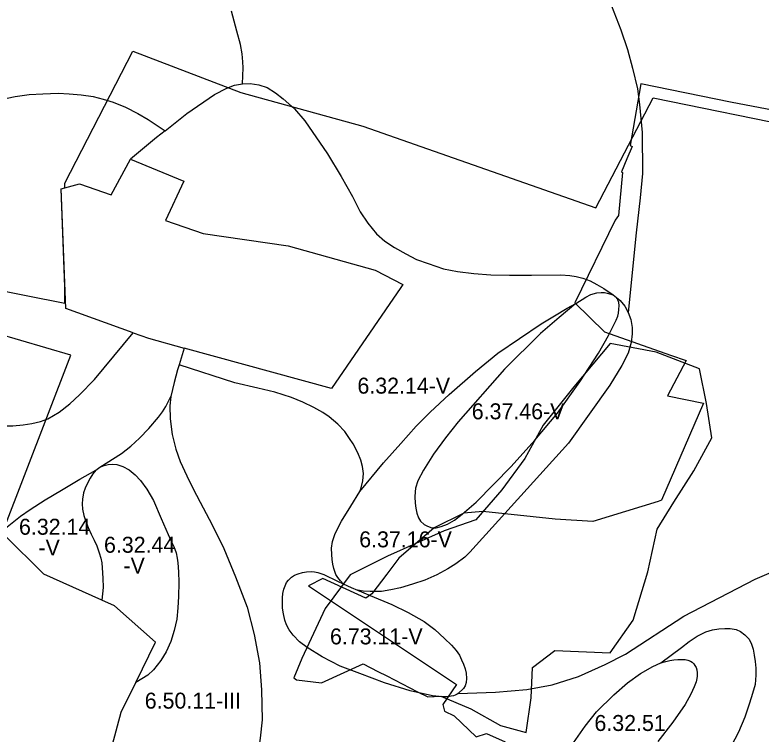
# Model space of a CAD drawing. Extents: x -555156 to -540209, y -1046851 to -1035695.
# Drawn here: x -544634.7 to -544167.7, y -1042567.7 to -1042117.3 of the extents above; entities that cross this region are included whole.
import ezdxf

# ---------------------------------------------------------------- set-up
doc = ezdxf.new("R2010")
doc.units = 0
for name, color, linetype in [('Vrstva 12', 7, 'Continuous'), ('Vrstva 27', 7, 'Continuous'), ('Vrstva 28', 7, 'Continuous'), ('Vrstva 29', 7, 'Continuous')]:
    doc.layers.add(name, color=color, linetype=linetype)

msp = doc.modelspace()

# ---------------------------------------------------------------- linework, layer by layer
at = {"layer": 'Vrstva 12'}
msp.add_lwpolyline([(-544150.62, -1042178.77), (-544186.87, -1042171.92), (-544242.89, -1042160.42), (-544249.66, -1042199.1), (-544248.44, -1042199.63), (-544251.6, -1042207.36), (-544254.98, -1042215.64), (-544254.37, -1042215.89), (-544256.8, -1042242.86), (-544258.96, -1042245.76), (-544284.29, -1042297.51), (-544265.75, -1042315.75), (-544224.34, -1042330.35), (-544214.54, -1042333.81), (-544226.14, -1042355.84), (-544203.79, -1042360.51), (-544230.02, -1042421.28), (-544232.13, -1042421.93), (-544272.91, -1042434.55), (-544296.56, -1042433.03), (-544341.92, -1042428.21), (-544353.62, -1042429.36), (-544372.27, -1042438.45), (-544394.46, -1042457.59), (-544401.95, -1042467.55), (-544411.26, -1042479.92), (-544415.04, -1042482.59), (-544442.07, -1042470.28), (-544450.93, -1042474.89), (-544358.23, -1042536.67), (-544366.89, -1042549.22), (-544365.9, -1042553.24), (-544359.86, -1042556.35), (-544346, -1042569.32), (-544339.58, -1042567.41), (-544327.89, -1042572.5)], dxfattribs=at)
at = {"layer": 'Vrstva 28'}
for points in [[(-544261.28, -1042111.58), (-544255.35, -1042126.64), (-544251.3, -1042138.91), (-544248.12, -1042150.57), (-544244.94, -1042163.51), (-544243.67, -1042173.47), (-544242.18, -1042190.86), (-544241.97, -1042216.52), (-544243.24, -1042231.79), (-544245.79, -1042253.84), (-544250.86, -1042303.69)], [(-544492.26, -1042160.44), (-544491.89, -1042150.48), (-544492.05, -1042146.73), (-544492.54, -1042141.61), (-544493.58, -1042135.79), (-544495.72, -1042127.48), (-544499.18, -1042114.88)], [(-544540.6, -1042189.78), (-544527, -1042179.03), (-544509.68, -1042167.04), (-544502.15, -1042163.07), (-544497.31, -1042161.34), (-544492.26, -1042160.44)], [(-544492.26, -1042160.44), (-544487.41, -1042160.17), (-544482.02, -1042161.07)], [(-544482.02, -1042161.07), (-544476.83, -1042162.8), (-544471.5, -1042165.98), (-544466.79, -1042169.79), (-544459.73, -1042176.02), (-544453.23, -1042183.71), (-544438.97, -1042204.34), (-544430.49, -1042218.55), (-544423.34, -1042231.03), (-544418.5, -1042240.6), (-544413.77, -1042247.75), (-544408.32, -1042254.3), (-544403.11, -1042259.02), (-544397.14, -1042262.89), (-544389.99, -1042267.01), (-544383.33, -1042270.4), (-544376.06, -1042273.07), (-544366.37, -1042276.22), (-544357.65, -1042277.92), (-544347.36, -1042279.13), (-544336.82, -1042279.98), (-544325.2, -1042280.22), (-544311.27, -1042280.22), (-544293.1, -1042280.1), (-544287.47, -1042280.42), (-544283.46, -1042281.11), (-544279.17, -1042282.22), (-544274.74, -1042283.88), (-544270.38, -1042286.03), (-544266.16, -1042288.59), (-544260.2, -1042292.61)], [(-544671.87, -1042176.14), (-544634.47, -1042168.33), (-544625.75, -1042167.12), (-544617.15, -1042166.75), (-544607.7, -1042166.39), (-544600.8, -1042166.75)], [(-544600.8, -1042166.75), (-544593.29, -1042167.24), (-544585.66, -1042168.33), (-544579.37, -1042170.02), (-544573.19, -1042171.96), (-544565.56, -1042174.99), (-544557.81, -1042179.11), (-544551.39, -1042182.75), (-544543.88, -1042187.71), (-544540.6, -1042189.78)], [(-544540.6, -1042189.78), (-544546.01, -1042194.06), (-544562.45, -1042207.72)], [(-544560.69, -1042316.32), (-544602.92, -1042301.05), (-544605.8, -1042226.13), (-544594.35, -1042223.17), (-544574.48, -1042229.9), (-544562.45, -1042207.72)], [(-544562.45, -1042207.72), (-544529.04, -1042221.35)], [(-544529.04, -1042221.35), (-544540.45, -1042246.04), (-544516.78, -1042254.25), (-544463.72, -1042261.88), (-544409.26, -1042277.15), (-544391.87, -1042286.17), (-544393.14, -1042288.02), (-544436.63, -1042351.24), (-544528.8, -1042325.91)], [(-544283.68, -1042297.99), (-544277.36, -1042293.95), (-544274.19, -1042292.45), (-544270.44, -1042291.38), (-544267.79, -1042291.07), (-544265.57, -1042291.22)], [(-544265.57, -1042291.22), (-544264.03, -1042291.54), (-544260.2, -1042292.61)], [(-544283.68, -1042297.99), (-544294.02, -1042306.69), (-544305.77, -1042316.87), (-544328.29, -1042339.05), (-544357.36, -1042372.13), (-544365.24, -1042382.22), (-544372.63, -1042392.28), (-544378.92, -1042402.33), (-544382.56, -1042409), (-544383.89, -1042413.6), (-544384.23, -1042416.04), (-544384.3, -1042419.08), (-544384.09, -1042423.03), (-544383.81, -1042426.21), (-544383.19, -1042429.26), (-544382.15, -1042432.31), (-544380.84, -1042434.38), (-544378.55, -1042436.46), (-544376.48, -1042437.43), (-544373.71, -1042438.54), (-544371.08, -1042438.54), (-544367.82, -1042437.71), (-544363.95, -1042436.32), (-544359.52, -1042433.76), (-544354.68, -1042429.95), (-544346.03, -1042422.41), (-544324.16, -1042400.11), (-544309.24, -1042383.63), (-544295.07, -1042366.67), (-544281.14, -1042347.16), (-544269.51, -1042329.22), (-544263.15, -1042318.02), (-544258.3, -1042308.4), (-544257.41, -1042306.05), (-544256.94, -1042304.03), (-544256.62, -1042301.7), (-544256.5, -1042299.36), (-544256.78, -1042297.35), (-544257.33, -1042295.65), (-544257.7, -1042294.98), (-544258.23, -1042294.23)], [(-544260.2, -1042292.61), (-544258.23, -1042294.23)], [(-544258.23, -1042294.23), (-544255.91, -1042296.14)], [(-544418.9, -1042415.72), (-544403.98, -1042397.9), (-544393.2, -1042385.67), (-544383.51, -1042374.88), (-544374.79, -1042366.04), (-544362.8, -1042355.01), (-544346.46, -1042340.59), (-544332.53, -1042329.2), (-544305.24, -1042310.83), (-544297.04, -1042305.69), (-544289.08, -1042300.98), (-544283.68, -1042297.99)], [(-544255.91, -1042296.14), (-544253.01, -1042299.67), (-544250.86, -1042303.69)], [(-544250.86, -1042303.69), (-544249.27, -1042308.12), (-544248.3, -1042312.96), (-544248.41, -1042317.05), (-544248.89, -1042322.5), (-544250.83, -1042329.16), (-544254.83, -1042336.92), (-544262.34, -1042349.16), (-544288.13, -1042385.39), (-544350, -1042453.86), (-544353.16, -1042456.85), (-544358.69, -1042461.01), (-544363.81, -1042464.19), (-544370.53, -1042468), (-544378.07, -1042471.32), (-544385.89, -1042473.75), (-544393.29, -1042476.03), (-544399.45, -1042477.42), (-544405.27, -1042478.39), (-544408.65, -1042478.48), (-544412.29, -1042478.48), (-544416.72, -1042478.09), (-544420.24, -1042477.51)], [(-544751.85, -1042358.18), (-544745.43, -1042357.58), (-544738.89, -1042357.82), (-544731.5, -1042359.63), (-544719.51, -1042363.88), (-544709.34, -1042367.15), (-544698.2, -1042370.18), (-544689.84, -1042371.51), (-544677.85, -1042372.84), (-544667.92, -1042373.69), (-544657.14, -1042374.42), (-544644.79, -1042374.66), (-544636.07, -1042374.54), (-544629.54, -1042374.04), (-544624.09, -1042373.19), (-544618.76, -1042371.98), (-544614.04, -1042370.16), (-544607.01, -1042366.16), (-544600.23, -1042360.95), (-544594.3, -1042355.14), (-544584.97, -1042345.68), (-544560.69, -1042316.32)], [(-544560.69, -1042316.32), (-544551.12, -1042319.78)], [(-544551.12, -1042319.78), (-544528.8, -1042325.91)], [(-544528.8, -1042325.91), (-544531.9, -1042336.37)], [(-544531.9, -1042336.37), (-544532.84, -1042339.53), (-544535.02, -1042347.52), (-544537.2, -1042356.37)], [(-544418.9, -1042415.72), (-544417.94, -1042413.5), (-544416.85, -1042409.14), (-544416.61, -1042404.54), (-544417.09, -1042400.18), (-544418.18, -1042396.06), (-544420, -1042391.57), (-544423.03, -1042386), (-544425.21, -1042382.48), (-544428.24, -1042378.24), (-544432.6, -1042373.52), (-544437.92, -1042368.91), (-544442.04, -1042366.25), (-544447.61, -1042363.22), (-544454.39, -1042359.82), (-544461.66, -1042356.8), (-544471.96, -1042353.52), (-544482.73, -1042351.1), (-544497.15, -1042347.71), (-544531.9, -1042336.37)], [(-544581.59, -1042400.45), (-544568.04, -1042391.88), (-544562.22, -1042387.4), (-544556.65, -1042382.43), (-544550.84, -1042376.25), (-544544.78, -1042369.22), (-544542.43, -1042365.95), (-544540.25, -1042362.47), (-544538.39, -1042358.67), (-544537.2, -1042356.37)], [(-544537.2, -1042356.37), (-544537.69, -1042362.18)], [(-544537.69, -1042362.18), (-544537.59, -1042370.27), (-544536.38, -1042379.97), (-544534.08, -1042389.3), (-544531.18, -1042397.05), (-544527.18, -1042405.9), (-544523.43, -1042413.77), (-544518.81, -1042422.36), (-544511.18, -1042436.57), (-544503.97, -1042451.41), (-544496.55, -1042469.23), (-544489.35, -1042488.31), (-544484.9, -1042505.27), (-544481.71, -1042523.06), (-544480.38, -1042540.03), (-544479.89, -1042558.69), (-544481.11, -1042570.32), (-544482.68, -1042580.98), (-544484.5, -1042589.47), (-544486.68, -1042597.1), (-544489.95, -1042604.37), (-544493.34, -1042610.19), (-544501.01, -1042619.24)], [(-544581.59, -1042400.45), (-544578.83, -1042399.48), (-544576.26, -1042398.79), (-544573.64, -1042398.58), (-544570.87, -1042398.79)], [(-544643.83, -1042441.2), (-544631.13, -1042431.14), (-544625.2, -1042427.02), (-544615.87, -1042421.08), (-544605.46, -1042415.03), (-544594.08, -1042408), (-544584.15, -1042402.39)], [(-544584.15, -1042402.39), (-544586.02, -1042404.76)], [(-544584.15, -1042402.39), (-544581.59, -1042400.45)], [(-544570.87, -1042398.79), (-544567.13, -1042400.11), (-544563.12, -1042402.12), (-544559.45, -1042405.23), (-544556.2, -1042408.9), (-544552.04, -1042414.23), (-544548.03, -1042421.5), (-544543.19, -1042432.58), (-544537.3, -1042446.08), (-544535.3, -1042450.26), (-544533.77, -1042454.27), (-544533.08, -1042457.46), (-544532.77, -1042460.49), (-544532.28, -1042466.07), (-544532.16, -1042472.85), (-544532.28, -1042481.46), (-544532.64, -1042488.61), (-544533.37, -1042495.63), (-544535.07, -1042502.78), (-544537.13, -1042509.81), (-544540.03, -1042516.11), (-544543.3, -1042521.69), (-544547.9, -1042527.5), (-544551.54, -1042530.77), (-544559.11, -1042535.46)], [(-544586.02, -1042404.76), (-544587.54, -1042407.4), (-544589.14, -1042410.03), (-544590.73, -1042413.77), (-544591.77, -1042416.67), (-544592.46, -1042420.48), (-544592.6, -1042423.53), (-544592.39, -1042426.85), (-544591.56, -1042430.73), (-544590.59, -1042433.98), (-544588.86, -1042438.35), (-544586.99, -1042442.43), (-544585.12, -1042446.24), (-544583.39, -1042449.84), (-544581.94, -1042454.27), (-544580.9, -1042457.6), (-544580.35, -1042460.5), (-544580.12, -1042463.64), (-544579.63, -1042469.95), (-544579.51, -1042475.88), (-544580.26, -1042483.76)], [(-544429.22, -1042473.54), (-544430.9, -1042471.66), (-544432.52, -1042469.63), (-544433.74, -1042467.65), (-544434.5, -1042465.87), (-544435.13, -1042463.89), (-544435.72, -1042461.2), (-544436.16, -1042458.32), (-544436.43, -1042455.31), (-544436.55, -1042451.24), (-544435.99, -1042447.15), (-544434.19, -1042442.03), (-544430.39, -1042434.41), (-544424.51, -1042424.93), (-544418.9, -1042415.72)], [(-544580.26, -1042483.76), (-544616.64, -1042467.62), (-544641.4, -1042442.86), (-544643.83, -1042441.2)], [(-544357.18, -1042542.23), (-544333.87, -1042541.38), (-544314.37, -1042539.69), (-544298.47, -1042536.93), (-544281.94, -1042531.63), (-544265.2, -1042524.21), (-544252.43, -1042517.58), (-544215.98, -1042493.83), (-544171.26, -1042470.72), (-544137.77, -1042456.3)], [(-544357.18, -1042542.23), (-544357.89, -1042542.69), (-544359.06, -1042543.25), (-544360.22, -1042543.68), (-544361.6, -1042544.02), (-544363.81, -1042544.29), (-544366.93, -1042544.29), (-544369.1, -1042544.22), (-544373.27, -1042543.67), (-544387.38, -1042540.63), (-544403.37, -1042535.5), (-544418.77, -1042529.77), (-544431.02, -1042525.06), (-544442.3, -1042519.32), (-544451.71, -1042513.5), (-544456.55, -1042509.83), (-544460.5, -1042505.75), (-544463.13, -1042502.42), (-544464.72, -1042499.37), (-544465.83, -1042496.26), (-544466.6, -1042492.48), (-544467.23, -1042488.88), (-544467.27, -1042485.28), (-544467.19, -1042482.31), (-544466.95, -1042479.7), (-544466.28, -1042476.97), (-544465.65, -1042474.92), (-544464.62, -1042472.74), (-544463.51, -1042471.2), (-544461.53, -1042469.38), (-544459.68, -1042468.23), (-544457.38, -1042467.24), (-544454.77, -1042466.53), (-544452.12, -1042466.05), (-544449.28, -1042465.93), (-544447.1, -1042466.09)], [(-544447.1, -1042466.09), (-544445, -1042466.49), (-544443.15, -1042467.04), (-544441.31, -1042467.73), (-544432.84, -1042471.85), (-544429.22, -1042473.54)], [(-544429.22, -1042473.54), (-544424.24, -1042475.85), (-544420.24, -1042477.51)], [(-544420.24, -1042477.51), (-544412.25, -1042480.82), (-544398.68, -1042486.52), (-544388.51, -1042491.61), (-544378.49, -1042497.18), (-544371.91, -1042502.17), (-544365.75, -1042507.85), (-544361.46, -1042511.93), (-544358.49, -1042515.26), (-544356.48, -1042518.23), (-544355.09, -1042521.21), (-544353.92, -1042523.84), (-544352.95, -1042526.89), (-544352.33, -1042529.59), (-544352.05, -1042532.91), (-544352.26, -1042535.4), (-544352.95, -1042537.41), (-544353.99, -1042539.07), (-544357.18, -1042542.23)], [(-544559.11, -1042535.46), (-544546.61, -1042510.14), (-544572.3, -1042487.29), (-544580.26, -1042483.76)], [(-544230.37, -1042523.13), (-544217.57, -1042513.43), (-544212.65, -1042509.69), (-544207.67, -1042506.37), (-544202.2, -1042503.67), (-544197.98, -1042502.35), (-544194.17, -1042501.8), (-544190.44, -1042501.52), (-544186.91, -1042501.66)], [(-544186.91, -1042501.66), (-544183.24, -1042502.15), (-544180.47, -1042503.46), (-544177.91, -1042505.54), (-544175.21, -1042508.24), (-544173.62, -1042511.36), (-544172.58, -1042514.61), (-544171.89, -1042518.35), (-544171.27, -1042522.3), (-544170.99, -1042526.45), (-544170.97, -1042530.85), (-544171.46, -1042536.54), (-544173.03, -1042542.36), (-544174.85, -1042548.42), (-544177.88, -1042557.02), (-544181.87, -1042566.47), (-544193.38, -1042588.93)], [(-544297.98, -1042611.14), (-544298.12, -1042608.51), (-544298.05, -1042605.26), (-544297.57, -1042602), (-544296.6, -1042598.33), (-544295.28, -1042594.45), (-544293.47, -1042590.09), (-544289.72, -1042581.49), (-544284.99, -1042573.25), (-544277.85, -1042562.83), (-544270.58, -1042553.74), (-544259.92, -1042543.2), (-544251.2, -1042535.56), (-544243.09, -1042529.75), (-544235.34, -1042525.27), (-544230.37, -1042523.13)], [(-544215.08, -1042521.06), (-544213.61, -1042521.34), (-544211.91, -1042522.01), (-544210.77, -1042522.68), (-544209.82, -1042523.67), (-544209.1, -1042524.7), (-544208.39, -1042526.01), (-544207.88, -1042527.39), (-544207.68, -1042529.41), (-544207.72, -1042531.35), (-544207.88, -1042532.93), (-544208.37, -1042535.05), (-544209.55, -1042538.16), (-544211.69, -1042542.73), (-544215.27, -1042549.22), (-544222.9, -1042560.13), (-544232.22, -1042572.37)], [(-544230.37, -1042523.13), (-544227.34, -1042522.17), (-544224.69, -1042521.61), (-544222.31, -1042521.26), (-544219.86, -1042521.06), (-544217.01, -1042520.94), (-544215.08, -1042521.06)], [(-544501.01, -1042619.24), (-544529.43, -1042602.92), (-544540.77, -1042596.41), (-544573.71, -1042574.3), (-544568.29, -1042554.04), (-544559.11, -1042535.46)]]:
    msp.add_lwpolyline(points, dxfattribs=at)
at = {"layer": 'Vrstva 29'}
for points in [[(-544703.695007, -1042278.034973), (-544603.439026, -1042297.830994), (-544603.439695, -1042287.530718), (-544605.8, -1042226.13), (-544603.443721, -1042225.520866), (-544603.443909, -1042222.624023), (-544560.869019, -1042140.021973), (-544493.361023, -1042165.859985), (-544416.973999, -1042186.939026), (-544271.184998, -1042238.117004), (-544235.268005, -1042169.153015), (-544141.085999, -1042188.367004)], [(-544642.609494, -1042442.033761), (-544599.630981, -1042330.317017), (-544709.434998, -1042298.135986)], [(-544460.148553, -1042532.48846), (-544458.47, -1042533.64), (-544442.89, -1042535.62), (-544416.76, -1042523.7), (-544407.58, -1042528.4), (-544401.92, -1042531.29), (-544382.66, -1042541.15), (-544376.273888, -1042544.417972), (-544368.159912, -1042543.932983), (-544349.252014, -1042551.862), (-544330.836975, -1042562.29303), (-544314.653015, -1042566.645996), (-544311.577026, -1042545.015991), (-544310.789001, -1042525.971985), (-544296.755981, -1042515.333008), (-544262.174011, -1042516.859009), (-544247.710999, -1042496.318909), (-544238.45697, -1042466.102905), (-544232.598999, -1042439.385986), (-544222.315979, -1042422.525024), (-544209.71991, -1042402.825989), (-544198.570007, -1042382.223999), (-544201.892029, -1042360.745972), (-544206.201904, -1042338.919006), (-544233.291992, -1042328.421997), (-544262.151978, -1042323.109985), (-544284.901978, -1042350.25), (-544304.026978, -1042374.16803), (-544315.453003, -1042394.997986), (-544329.844971, -1042414.780029), (-544346.187988, -1042433.609985), (-544365.981995, -1042440.382996), (-544401.460999, -1042456.362), (-544424.770996, -1042467.896912), (-544440.570984, -1042489.072998), (-544455.031006, -1042520.320984), (-544460.148553, -1042532.48846)]]:
    msp.add_lwpolyline(points, dxfattribs=at)

# ---------------------------------------------------------------- texts
at = {"layer": 'Vrstva 27'}
for s, p in [('6.32.14-V', (-544420.310884, -1042354.48)), ('6.37.46-V', (-544348.737974, -1042370.55)), ('6.32.14', (-544632.153149, -1042442.84)), ('6.37.16-V', (-544419.187974, -1042450.73)), ('6.32.44', (-544578.943149, -1042454.13)), ('-V', (-544619.957104, -1042455.84)), ('-V', (-544566.747104, -1042467.13)), ('6.73.11-V', (-544437.491006, -1042511.51)), ('6.50.11-III', (-544553.436548, -1042551.76)), ('6.32.51', (-544271.953394, -1042565.75))]:
    msp.add_text(s, height=10, dxfattribs=at).set_placement(p)

doc.saveas('drawing.dxf')
